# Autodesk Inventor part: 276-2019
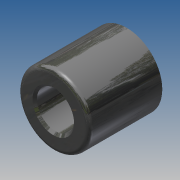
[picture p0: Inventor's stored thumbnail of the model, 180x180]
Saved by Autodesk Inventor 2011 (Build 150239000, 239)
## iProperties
Company: Autodesk Inc.
Created: 2010-06
Part Number: 276-2019
Document SubType Name: Modeling
Designer: Autodesk Inc.
Density: 1 g/cm^3
Catalog Web Link: http://www.vexrobotics.com/spacers.html
Description: A spacer is used to create a space between two objects, often to properly position them.
Vendor: Innovation First, Inc.
Author: Autodesk Inc.
Title: VEX Robotics Kit of Parts
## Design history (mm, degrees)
sketch "Sketch1"
  geometry: C1 r 4.064 at (0, 0); 1 further point
  constraints: 1 centre point, 1 coincident
  dimensions: "d0" = 8.128 diameter of C1
extrude "Extrusion1" new body sketch "Sketch1" distance "d1" = 8.382; taper "d2" = 0 deg
sketch "Sketch2"
  geometry: C1 r 4.064 at (0, 0) reference
hole "Hole1" sketch "Sketch2" at (0, 0) diameter "d3" = 4.2418; stored, may be unused: countersink angle "d7" = 82 deg, drill point angle "d9" = 118 deg; dims "d4" = 19.05, "d5" = 9.525, "d6" = 6.35, "d8" = 25.4
fillet "Fillet1" dims "d10" = 0.508
chamfer "Chamfer1" distance "d11" = 0.254; stored, may be unused: second distance "d12" = 3.175, angle "d13" = 45 deg
body "Solid1"
